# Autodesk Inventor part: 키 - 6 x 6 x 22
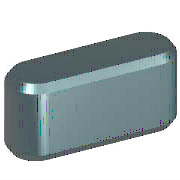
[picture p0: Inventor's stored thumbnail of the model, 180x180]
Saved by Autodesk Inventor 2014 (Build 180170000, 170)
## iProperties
IsCustomPart: 1
Created: 2012-02
Part Number: 키 - 6 x 6 x 22
Material: 강철, 연강
Description: 키 및 해당 키홈
Document SubType Name: Modeling
Standard: KS B 1311
Designer: mduedu
Standards Organization: KS
Language: ko-KR
Size Designation: 6 x 6 x 22
Categories: <MemberInstance><Categories><Category DisplayName="샤프트 부품" InternalName="7f7aeb1f-a693-4053-b835-cee3144e0d98" Mnemonic="SHFT"><Category DisplayName="키" Interna
Density: 7.86 g/cm^3
Mass: 5.79788 g
Surface Area: 5.294 cm^2
Volume: 0.737644 cm^3
Appearance: Yellow
Author: mduedu
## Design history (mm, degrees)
sketch "스케치1"
  geometry: L1 (3, 3)-(19, 3); L2 (19, -3)-(3, -3); L3 (0, 9.4)-(0, -7.4) reference; L4 (-5, 0)-(30, 0) reference; L5 (22, 0)-(22, 7); A1 r 3 centre (3, 0) between (3, 3) and (3, -3); A2 r 3 centre (19, 0) between (19, -3) and (19, 3)
  constraints: 6 end point, 5 point on circle, 4 tangent, 3 point on line, 2 centre point, 1 horizontal, 1 parallel, 1 perpendicular
  dimensions: "d0" = 3 radius of A1 (= 0.5 x PB); "d13" = 3 radius of A2 (= 0.5 x PB); "d14" = 22 distance between parallel lines of L5 L3 (= NLG)
extrude "본체1" new body sketch "스케치1" taper "d3" = 0 deg; stored distance "d4" = 10
workplane "Work Plane3"
body "Solid1"
workplane "Work Plane1"
workplane "Work Plane2"
chamfer "모따기1" distance "d8" = 0.4 (= PHH); stored, may be unused: second distance "d9" = 0.4 (= PHH), angle "d15" = 45 deg
other parameters: "d1" = -3.5 (= -PNT), "d2" = 2.5 (= PH - PNT), "NLG" = 22 [user parameter; used in 3 equation terms], "PB" = 6 [user parameter; used in 2 equation terms], "PNT" = 3.5 [user parameter; used in 2 equation terms], "PH" = 6 [user parameter; used in 1 equation term], "PHH" = 0.4 [user parameter; used in 2 equation terms], "d10" = 0, "d16" = 0, "d17" = 0, "d18" = 0, "WDMIN" = 17 [user parameter], "PLB2" = 22 (= NLG) [user parameter], "WDMAX" = 22 [user parameter], "PLB1" = 22 (= NLG) [user parameter], "RR" = 0.16 [user parameter], "PUEB" = 2.8 [user parameter]
